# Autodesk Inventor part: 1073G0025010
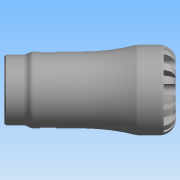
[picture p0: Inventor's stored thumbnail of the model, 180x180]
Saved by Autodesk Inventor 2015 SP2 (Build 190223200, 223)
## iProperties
Created: 2016-12
Part Number: 1073G0025010
Material: Generic
Description: PLASSON FEMALE INTEGRAL BRASS THREAD 25X1" G SERIES 1
Document SubType Name: Modeling
Designer: KIM
Density: 1 g/cm^3
Appearance: Default
Author: KIM
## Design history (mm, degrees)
derived "1073G.ipt"
feature "Solid1::1073G.ipt"
tag "TaggingFeature1"
body "Solid1"
other parameters: "d0" = 89, "d1" = 20.16, "d2" = 25, "d3" = 31.25, "d4" = 47, "d6" = 48, "d8" = 39.95, "d13" = 6.3, "d14" = 6.3, "d15" = 0, "d17" = 360 deg, "d19" = 8 deg, "d20" = 0.5, "d21" = 0.5, "d22" = 8 deg, "d24" = 0, "d26" = 360 deg, "d32" = 4.7, "d33" = 4.7, "d39" = 0.90873, "d42" = 30.291, "d43" = 36.66, "d46" = 2.08333, "d47" = 13.5, "d48" = 28.77645, "d50" = 9.075, "d51" = 0.47, "d54" = 8.75, "d55" = 5.5, "d57" = 12.348, "d58" = 0, "d68" = 360 deg, "d72" = 0.5, "d74" = 0, "d76" = 7.4375, "d_" = 25, "E_" = 47, "H_" = 89, "l_" = 48, "G_" = 30.291, "l_2" = 13.5, "d9" = 7.875, "d11" = 47, "d12" = 31.25, "d49" = 27.5
